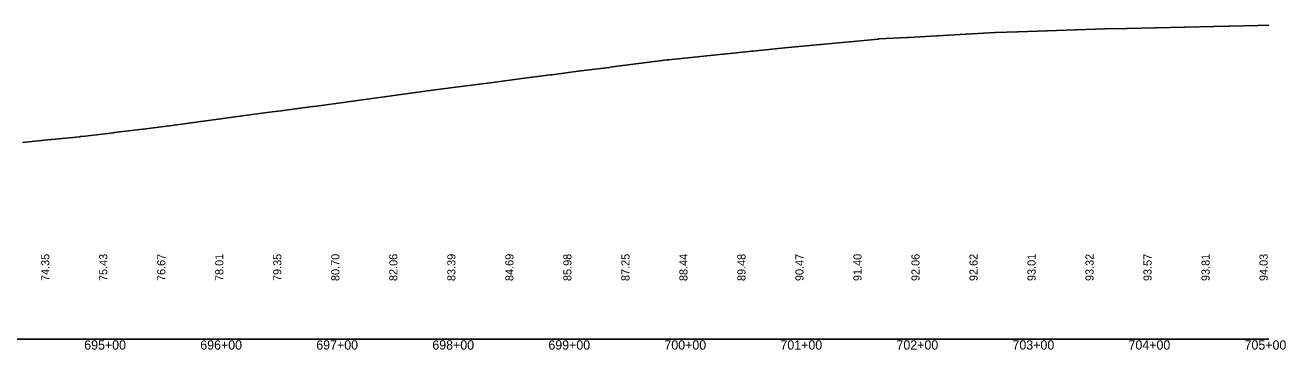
# Model space of a CAD drawing. Extents: x 2526761 to 2530854, y 882903 to 888012.
# Drawn here: x 2529767 to 2530854, y 887503 to 887782 of the extents above; entities that cross this region are included whole.
import ezdxf

# ---------------------------------------------------------------- set-up
doc = ezdxf.new("R2010")
doc.units = 0
for name, color, linetype in [('RD_DDB_Profile_EX', 7, 'Continuous'), ('RD_DDB_StaTX', 7, 'Continuous'), ('RD_DDB_StripGrade', 7, 'Continuous'), ('RD_GPK_Profile_Cell', 7, 'Continuous')]:
    doc.layers.add(name, color=color, linetype=linetype)

msp = doc.modelspace()

# ---------------------------------------------------------------- linework, layer by layer
at = {"layer": 'RD_DDB_Profile_EX'}
for points in [[(2530622.9, 887776.6), (2530647.4, 887777.4), (2530648, 887777.4), (2530672.4, 887778.2), (2530673, 887778.2), (2530697.7, 887779), (2530716.3, 887779.4), (2530716.8, 887779.4), (2530741.3, 887780), (2530741.8, 887780), (2530766.3, 887780.6), (2530766.8, 887780.6), (2530791.3, 887781.2), (2530791.6, 887781.2), (2530804.6, 887781.5), (2530805, 887781.5), (2530829.6, 887782), (2530830, 887782), (2530839, 887782.2)], [(2529764.9, 887681.4), (2529789.3, 887683.8), (2529789.9, 887683.9), (2529814.3, 887686.3), (2529814.9, 887686.4), (2529818.9, 887686.9), (2529843.4, 887689.7), (2529843.9, 887689.8), (2529868.5, 887692.7), (2529868.9, 887692.7), (2529891.2, 887695.7), (2529891.5, 887695.8), (2529916.5, 887699.1), (2529937.7, 887701.9), (2529962.7, 887705.3), (2529980.1, 887707.6), (2529987.7, 887708.6), (2530012.6, 887712), (2530018.3, 887712.7), (2530043.2, 887716.1), (2530068.2, 887719.5), (2530093.2, 887723), (2530118.2, 887726.4), (2530120.2, 887726.6), (2530145.2, 887729.9), (2530170.2, 887733.1), (2530195.2, 887736.4), (2530219.9, 887739.6), (2530221.2, 887739.7), (2530245.8, 887742.9), (2530246.2, 887742.9), (2530270.8, 887746), (2530271.2, 887746.1), (2530295.7, 887749.2), (2530296.2, 887749.3), (2530320.6, 887752.4), (2530321.2, 887752.4), (2530321.5, 887752.5), (2530343.9, 887754.8), (2530368.4, 887757.3), (2530368.9, 887757.4), (2530393.5, 887759.9), (2530393.8, 887760), (2530394.3, 887760), (2530419, 887762.6), (2530428, 887763.4), (2530452.5, 887765.7), (2530453, 887765.7), (2530477.4, 887768), (2530478, 887768), (2530502.3, 887770.3), (2530503, 887770.4), (2530527.4, 887771.7), (2530528, 887771.8), (2530528.6, 887771.8), (2530553, 887773.2), (2530553.5, 887773.2), (2530578, 887774.6), (2530578.5, 887774.6), (2530603, 887776), (2530603.4, 887776), (2530622.4, 887776.6), (2530622.9, 887776.6)]]:
    msp.add_lwpolyline(points, dxfattribs=at)
at = {"layer": 'RD_GPK_Profile_Cell'}
msp.add_line((2526839, 887512.1), (2530839, 887512.1), dxfattribs=at)

# ---------------------------------------------------------------- texts
at = {"layer": 'RD_DDB_StaTX'}
for s, p in [('695+00', (2529818.1, 887503.1)), ('696+00', (2529918.1, 887503.1)), ('697+00', (2530018.1, 887503.1)), ('698+00', (2530118.1, 887503.1)), ('699+00', (2530218.1, 887503.1)), ('700+00', (2530318.1, 887503.1)), ('701+00', (2530418.1, 887503.1)), ('702+00', (2530518.1, 887503.1)), ('703+00', (2530618.1, 887503.1)), ('704+00', (2530718.1, 887503.1)), ('705+00', (2530818.1, 887503.1))]:
    msp.add_text(s, height=8, dxfattribs=at).set_placement(p)
at = {"layer": 'RD_DDB_StripGrade'}
for s, p in [('74.35', (2529788, 887562.1)), ('75.43', (2529838, 887562.1)), ('76.67', (2529888, 887562.1)), ('78.01', (2529938, 887562.1)), ('79.35', (2529988, 887562.1)), ('80.70', (2530038, 887562.1)), ('82.06', (2530088, 887562.1)), ('83.39', (2530138, 887562.1)), ('84.69', (2530188, 887562.1)), ('85.98', (2530238, 887562.1)), ('87.25', (2530288, 887562.1)), ('88.44', (2530338, 887562.1)), ('89.48', (2530388, 887562.1)), ('90.47', (2530438, 887562.1)), ('91.40', (2530488, 887562.1)), ('92.06', (2530538, 887562.1)), ('92.62', (2530588, 887562.1)), ('93.01', (2530638, 887562.1)), ('93.32', (2530688, 887562.1)), ('93.57', (2530738, 887562.1)), ('93.81', (2530788, 887562.1)), ('94.03', (2530838, 887562.1))]:
    msp.add_text(s, height=7, rotation=90, dxfattribs=at).set_placement(p)

doc.saveas('drawing.dxf')
